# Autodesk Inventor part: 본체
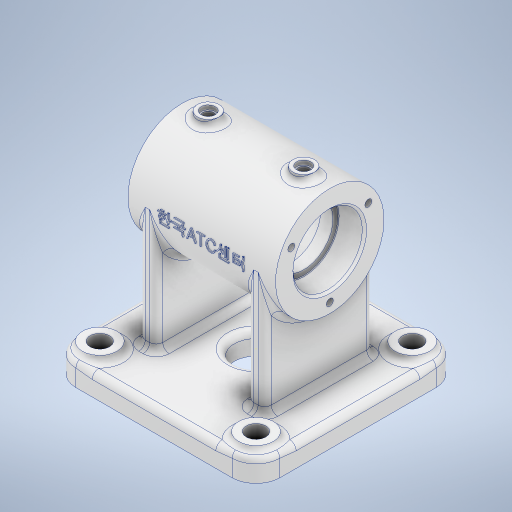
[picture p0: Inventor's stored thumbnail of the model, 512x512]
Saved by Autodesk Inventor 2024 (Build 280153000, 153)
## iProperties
Created: 2025-10
Part Number: 본체
Material: 알루미늄 6061
Document SubType Name: Modeling
Designer: EDU03
Density: 2.7 g/cm^3
Appearance: 알루미늄 - 평지
Mass: 505.839 g
Surface Area: 503.745 cm^2
Volume: 187.348 cm^3
Author: EDU03
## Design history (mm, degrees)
sketch "스케치1"
  geometry: L1 (47, -47)-(-47, -47); L2 (-47, -47)-(-47, 47); L3 (-47, 47)-(47, 47); L4 (47, 47)-(47, -47); 3 further points
  constraints: 8 end point, 2 midpoint, 2 parallel, 1 horizontal, 1 horizontal alignment, 1 perpendicular, 1 vertical alignment
  dimensions: "d0" = 94 distance of L1.start L1.end; "d1" = 94 distance of L3.end L1.start
extrude "돌출1" new body sketch "스케치1" distance "d2" = 10; taper "d3" = 0 deg
node "작업 평면1"
sketch "스케치2"
  geometry: L1 (0, 47)-(0, -47) reference; C1 r 25 at (66, 0); 2 further points
  constraints: 1 centre point, 1 horizontal alignment, 1 midpoint
  dimensions: "d5" = 66 distance from line of L1 C1.centre; "d6" = 50 diameter of C1
extrude "돌출2" join sketch "스케치2" stored distance "d7" = 68; taper "d8" = 0 deg
sketch "스케치4"
  geometry: L1 (-29, 25)-(-21, 25); L2 (-21, 25)-(-21, -25); L3 (-21, -25)-(-29, -25); L4 (-29, -25)-(-29, 25); L5 (21, 25)-(29, 25); L6 (29, 25)-(29, -25); L7 (29, -25)-(21, -25); L8 (21, -25)-(21, 25); L9 (-21, 0)-(21, 0); 3 further points
  constraints: 18 end point, 4 midpoint, 4 parallel, 3 perpendicular, 2 horizontal, 2 horizontal alignment, 1 coincident, 1 point on line
  dimensions: "d14" = 50 distance of L3.end L1.start; "d15" = 8 distance of L1.start L1.end; "d16" = 8 distance of L5.start L5.end; "d17" = 42 distance between parallel lines of L8 L2
extrude "돌출3" join sketch "스케치4" stored distance "d18" = 68; taper "d19" = 0 deg
sketch "스케치5"
  geometry: 1 further point
fillet "모깎기1" dims "d20" = 11
sketch "스케치6"
  geometry: C1 r 8 at (-36, 36); C2 r 8 at (36, 36); C3 r 8 at (36, -36); C4 r 8 at (-36, -36); A1 r 11 centre (-36, 36) between (-36, 47) and (-47, 36) reference; A2 r 11 centre (36, 36) between (47, 36) and (36, 47) reference; A3 r 11 centre (36, -36) between (36, -47) and (47, -36) reference; A4 r 11 centre (-36, -36) between (-47, -36) and (-36, -47) reference; 1 further point
  constraints: 4 centre point, 4 coincident
  dimensions: "d21" = 16 diameter of C1; "d22" = 16 diameter of C2; "d23" = 16 diameter of C3; "d24" = 16 diameter of C4
extrude "돌출4" join sketch "스케치6" distance "d25" = 3; taper "d26" = 0 deg
sketch "스케치7"
  geometry: C1 r 8 at (0, 0) reference; C2 r 8 at (72, 0) reference; C3 r 8 at (72, 72) reference; C4 r 8 at (0, 72) reference; 5 further points
  constraints: 4 coincident
hole "구멍1" sketch "스케치7" at (0, 0), (72, 0), (72, 72), (0, 72) diameter "d27" = 9; stored, may be unused: countersink angle "d31" = 90 deg, drill point angle "d33" = 118 deg; dims "d28" = 6, "d29" = 4, "d30" = 2, "d32" = 8
sketch "스케치8"
  geometry: C1 r 10 at (0, 0); 1 further point
  constraints: 1 centre point, 1 coincident
  dimensions: "d34" = 20 diameter of C1
extrude "돌출5" cut sketch "스케치8" extent not by distance; stored distance "d35" = 0; taper "d36" = 0 deg
sketch "스케치9"
  geometry: L1 (-34, 91)-(-34, 41) reference; L2 (-34, 66)-(34, 66); L3 (34, 41)-(34, 91) reference; L4 (-34, 66)-(-22, 66); L5 (-22, 66)-(-22, 81.7); L6 (-22.3, 82)-(-34, 82); L7 (-34, 82)-(-34, 66); L8 (-22, 66)-(-16.258, 66); L9 (-16.258, 66)-(-16.258, 79.5); L10 (-16.258, 79.5)-(-22, 79.5); L11 (-22, 79.5)-(-22, 66); L12 (-16.258, 79.5)-(-5, 86); L13 (-5, 86)-(5, 86); L14 (5, 86)-(16.258, 79.5); L15 (34, 66)-(22, 66); L16 (22, 66)-(22, 81.7); L17 (22.3, 82)-(34, 82); L18 (34, 82)-(34, 66); L19 (22, 66)-(16.258, 66); L20 (16.258, 66)-(16.258, 79.5); L21 (16.258, 79.5)-(22, 79.5); L22 (22, 79.5)-(22, 66); A1 r 0.3 centre (-22.3, 81.7) between (-22, 81.7) and (-22.3, 82); A2 r 0.3 centre (22.3, 81.7) between (22.3, 82) and (22, 81.7); 9 further points
  constraints: 40 end point, 8 parallel, 5 horizontal, 4 midpoint, 4 perpendicular, 4 point on circle, 4 point on line, 4 tangent, 2 centre point, 1 equal radius, 1 vertical alignment
  dimensions: "d37" = 12 distance of point (-22, 82) L6.end; "d38" = 30 deg angle of L2 L12; "d40" = 30 deg angle of L2 L14; "d41" = 32 diameter of L6 L2; "d42" = 10 distance of L13.end L12.end; "d43" = 32 diameter of L17 L2; "d44" = 27 diameter of L21 L2; "d45" = 27 diameter of L10 L2; "d46" = 40 diameter of L13 L2; "d47" = 12 distance of point (22, 82) L17.end; "d48" = 0.3 radius of A1
revolve "회전1" sketch "스케치9" stored, may be unused: angle "d49" = 90 deg
node "작업 평면2"
sketch "스케치10"
  geometry: L1 (34, -25)-(34, 25) reference; L2 (-34, 25)-(-34, -25) reference; C1 r 5 at (22, 0); C2 r 5 at (-22, 0); 1 further point
  constraints: 2 centre point, 2 horizontal alignment
  dimensions: "d51" = 12 distance from line of L1 C1.centre; "d52" = 12 distance from line of L2 C2.centre; "d53" = 10 diameter of C1; "d54" = 10 diameter of C2
extrude "돌출6" join sketch "스케치10" stored distance "d55" = 10; taper "d56" = 0 deg
sketch "스케치11"
  geometry: C1 r 5 at (0, 0) reference; C2 r 5 at (44, 0) reference; 3 further points
  constraints: 2 coincident
hole "구멍2" sketch "스케치11" at (0, 0), (44, 0) diameter "d57" = 5.1881; stored, may be unused: countersink angle "d61" = 90 deg, drill point angle "d63" = 118 deg; dims "d58" = 25.25, "d59" = 6.6, "d60" = 2, "d62" = 30.5
sketch "스케치12"
  geometry: C1 r 25 at (0, 0) reference; A1 r 20.5 centre (0, 0) between (-17.754, 10.25) and (17.754, 10.25); 2 further points
  constraints: 3 point on circle, 1 centre point, 1 coincident, 1 vertical alignment
  dimensions: "d64" = 41 diameter of A1; "d65" = 120 deg dimension on A1.centre A1.end point (0, -20.5); "d66" = 120 deg dimension on A1.centre A1.start point (0, -20.5)
hole "구멍3" sketch "스케치12" at (-17.754, 10.25), (17.754, 10.25), (0, -20.5) diameter "d67" = 3.242; stored, may be unused: countersink angle "d71" = 90 deg, drill point angle "d73" = 118 deg; dims "d68" = 8, "d69" = 6.6, "d70" = 2, "d72" = 10
node "작업 평면3"
node "작업 평면4"
sketch "스케치13"
  geometry: C1 r 6 at (0, 0); 2 further points
  constraints: 2 coincident, 1 centre point
  dimensions: "d75" = 12 diameter of C1
extrude "돌출7" join sketch "스케치13" stored distance "d76" = 10; taper "d77" = 0 deg
sketch "스케치14"
  geometry: C1 r 6 at (0, 0) reference; 2 further points
  constraints: 1 coincident
hole "구멍4" sketch "스케치14" at (0, 0) diameter "d78" = 5.1881; stored, may be unused: countersink angle "d82" = 90 deg, drill point angle "d84" = 0 deg; dims "d79" = 18, "d80" = 4, "d81" = 2, "d83" = 24
fillet "모깎기2" dims "d85" = 3
fillet "모깎기3" dims "d86" = 3
fillet "모깎기4" dims "d87" = 3
fillet "모깎기5" dims "d88" = 3
fillet "모깎기6" dims "d89" = 3
node "작업 평면5"
sketch "스케치15"
  geometry: L1 (-36, 0)-(36, 0) reference; 2 further points
  constraints: 1 vertical alignment, 1 other
  dimensions: "d91" = 66 distance from line of L1 point (0, 66)
feature "엠보싱1" sketch "스케치15" dims "d0" = 94, "d1" = 94, "d14" = 50, "d15" = 8, "d16" = 8, "d17" = 42, "d92" = 0.5, "d93" = 0
fillet "모깎기7" dims "d94" = 3
chamfer "모따기1" distance "d95" = 1; stored, may be unused: second distance "d96" = 2, angle "d97" = 45 deg
fillet "모깎기8" dims "d98" = 3
feature "Ϣ耀Ϥ耀Ϧ耀Ϩ耀Ϫ耀Ϭ耀Ϯ耀ϰ耀" dims "d0" = 94, "d1" = 94, "d2" = 10, "d3" = 0, "d4" = 66, "d5" = 66, "d6" = 50, "d7" = 68, "d8" = 0, "d14" = 50, "d15" = 8, "d16" = 8, "d17" = 42, "d18" = 68, "d19" = 0, "d20" = 11, "d21" = 16, "d22" = 16, "d23" = 16, "d24" = 16, "d25" = 3, "d26" = 0, "d27" = 9, "d28" = 6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
node "솔리드1"
mirror "미러1"
feature "A9D066F2-1C7D-4E18-AEED-F7BC21143FA4" dims "d67" = 3.242, "d68" = 8, "d69" = 6.6, "d70" = 2, "d71" = 90 deg, "d72" = 10, "d73" = 118 deg
